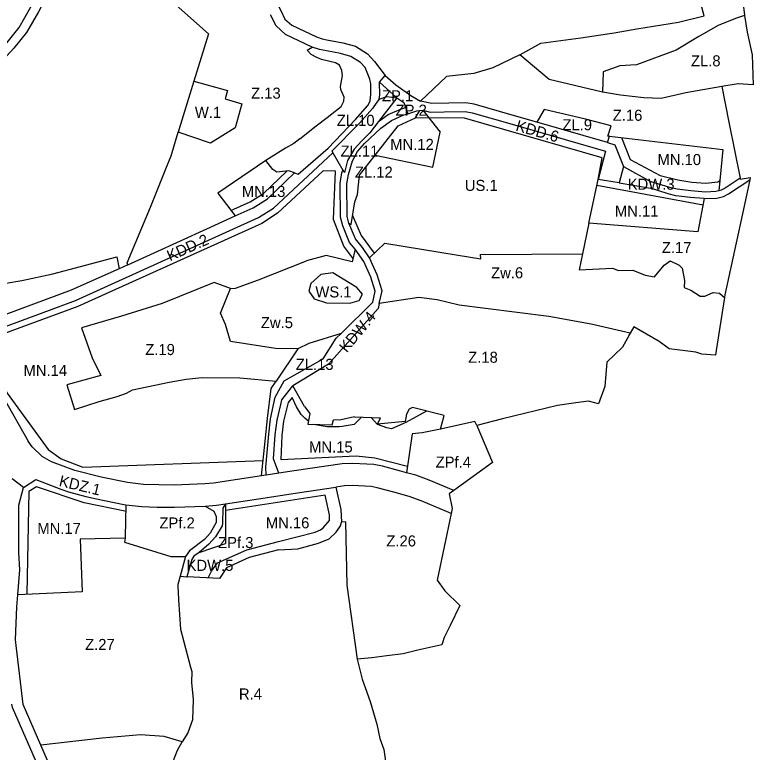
# Model space of a CAD drawing. Extents: x 7425478 to 7427982, y 5538517 to 5541171.
# Drawn here: x 7426110 to 7426777, y 5539161 to 5539827 of the extents above; entities that cross this region are included whole.
import ezdxf

# ---------------------------------------------------------------- set-up
doc = ezdxf.new("R2010")
doc.units = 0
for name, color, linetype in [('linie_rozgraniczajace', 7, 'Continuous'), ('linie_zabudowy_nieprzekraczalne', 7, 'Continuous'), ('oznaczenia_przeznaczen', 7, 'Continuous')]:
    doc.layers.add(name, color=color, linetype=linetype)

msp = doc.modelspace()

# ---------------------------------------------------------------- linework, layer by layer
at = {"layer": 'linie_rozgraniczajace'}
for p, q in [((7426285, 5539810.09), (7426271.89, 5539767.33)), ((7426439.61, 5539766.29), (7426444.81, 5539772.3)), ((7426455.35, 5539752.15), (7426439.61, 5539766.29)), ((7426455.35, 5539752.15), (7426438.67, 5539730.7)), ((7426463.07, 5539743.41), (7426465.29, 5539737.72)), ((7426475.94, 5539740.64), (7426478.73, 5539740.85)), ((7426478.73, 5539740.85), (7426494.38, 5539721.07)), ((7426645.63, 5539711.74), (7426581.74, 5539730.17)), ((7426647.49, 5539717.47), (7426646.05, 5539717.64)), ((7426397.35, 5539702.43), (7426406.5, 5539686.89)), ((7426643.73, 5539703.89), (7426637.31, 5539678.48)), ((7426749.94, 5539705.41), (7426746.33, 5539668.14)), ((7426406.5, 5539686.89), (7426407.9, 5539684.53)), ((7426660.09, 5539690.13), (7426656.36, 5539675.2)), ((7426283.56, 5539633.75), (7426309.14, 5539645.38)), ((7426628.89, 5539638.83), (7426623.22, 5539611.25)), ((7426212.06, 5539601.25), (7426204.28, 5539597.74)), ((7426204.28, 5539597.74), (7426172.52, 5539583.41)), ((7426365.83, 5539525.31), (7426346.21, 5539496)), ((7426371.89, 5539473.29), (7426361.19, 5539491.88)), ((7426371.89, 5539473.29), (7426376.65, 5539466.93)), ((7426437.87, 5539457.23), (7426440.63, 5539463)), ((7426348.68, 5539412.92), (7426337.3, 5539411.17)), ((7426117.82, 5539399.93), (7426107.74, 5539407.9)), ((7426337.3, 5539411.17), (7426333.03, 5539410.51)), ((7426300.44, 5539385.25), (7426300.52, 5539349.55)), ((7426276.69, 5539341.46), (7426300.52, 5539349.55))]:
    msp.add_line(p, q, dxfattribs=at)
for points in [[(7426172.93, 5539910.75), (7426157.78, 5539880.88), (7426131.38, 5539829.96), (7426120.78, 5539811.26), (7426109.12, 5539796.88), (7426076.6, 5539761.74), (7426068.87, 5539756.4), (7426052.03, 5539754.96), (7426040.49, 5539757.6), (7426024.63, 5539763.12), (7426003.8, 5539773.22), (7425997.61, 5539775.55), (7425990.1, 5539777.21), (7425982.57, 5539778.07)], [(7426172.93, 5539910.75), (7426199.52, 5539886.77), (7426237.04, 5539852.97), (7426285, 5539810.09)], [(7425861.28, 5539789.58), (7425876.14, 5539788.48), (7425917.05, 5539790.68), (7425930.12, 5539791.21), (7425946.2, 5539790.43), (7425991.44, 5539785.11), (7425999.89, 5539783.23), (7426006.95, 5539780.58), (7426027.7, 5539770.52), (7426042.71, 5539765.3), (7426052.59, 5539763.04), (7426066.07, 5539764.19), (7426071.32, 5539767.83), (7426103.07, 5539802.12), (7426114.14, 5539815.78), (7426124.35, 5539833.77), (7426150.65, 5539884.52), (7426159.34, 5539901.8)], [(7426341.76, 5539847.53), (7426350.65, 5539830.3), (7426354.22, 5539823.36), (7426360.39, 5539817.82), (7426382.72, 5539807.31), (7426387.89, 5539805.46), (7426392.07, 5539804.68), (7426406.6, 5539801.94), (7426417.95, 5539798.68), (7426428.88, 5539791.94), (7426435.25, 5539784.9), (7426444.81, 5539772.3)], [(7426768.52, 5539834.05), (7426769.46, 5539826.99), (7426769.54, 5539826.5), (7426771.95, 5539811.37), (7426776.4, 5539790.88), (7426777.36, 5539763.92), (7426763.76, 5539764.86), (7426748.98, 5539762.31), (7426755.39, 5539730.27), (7426765.55, 5539679.57), (7426765.7, 5539678.8), (7426774.69, 5539680.3), (7426774.22, 5539678.13), (7426767.58, 5539647.36), (7426751.75, 5539574), (7426751.28, 5539571.84), (7426751.27, 5539571.76), (7426743.93, 5539523.95), (7426743.21, 5539519.72), (7426730.8, 5539520.4), (7426725.56, 5539522.24), (7426701.31, 5539525.35), (7426692.21, 5539532.01), (7426680.76, 5539538.65), (7426669.32, 5539545.29), (7426666.18, 5539539.43), (7426666.07, 5539539.46), (7426666.03, 5539539.39), (7426665.03, 5539537.57), (7426665.14, 5539537.55), (7426659.14, 5539526.99), (7426645.04, 5539513.3), (7426643.15, 5539491.25), (7426637.58, 5539475.74), (7426628.35, 5539478.04), (7426617.12, 5539476.46), (7426600.57, 5539474.13), (7426550.91, 5539461.99), (7426527.49, 5539456.05), (7426541.81, 5539422.74), (7426506.76, 5539397.33), (7426502.62, 5539394.33), (7426505.39, 5539381.09), (7426504.43, 5539376.49), (7426491.73, 5539316.21), (7426498.72, 5539306.75), (7426512.27, 5539293.31), (7426503.42, 5539275.38), (7426497.96, 5539264.52), (7426496.44, 5539259.78), (7426495.87, 5539258.02), (7426474.37, 5539252.97), (7426460.89, 5539249.8), (7426446.27, 5539247.88), (7426432.78, 5539246.23), (7426419.48, 5539244.98), (7426423.98, 5539226.92), (7426431.18, 5539206.84), (7426437.31, 5539186.31), (7426439.93, 5539173.23), (7426443.46, 5539163.33), (7426447.85, 5539134.04)], [(7426566.31, 5539790.94), (7426585.56, 5539801.43), (7426621.44, 5539806.39), (7426651.66, 5539810.88), (7426672.2, 5539814.35), (7426709.79, 5539820.37), (7426732.96, 5539826.26), (7426730.15, 5539837.31)], [(7426378.9, 5539798.05), (7426354.8, 5539809.4), (7426346.17, 5539817.15), (7426341, 5539827.19)], [(7426769.54, 5539826.5), (7426761.3, 5539823.94), (7426745.75, 5539817.53), (7426728.11, 5539807.63), (7426707.67, 5539795.31), (7426671.73, 5539781.82), (7426656.78, 5539781.14), (7426641.67, 5539775.58), (7426641.12, 5539757.11)], [(7426362.77, 5539684.28), (7426366.04, 5539683.02), (7426393.22, 5539706.79), (7426417.96, 5539732.64), (7426429.18, 5539745.33), (7426431.25, 5539749.27), (7426431.92, 5539755.33), (7426431.76, 5539764.77), (7426430.9, 5539769.11), (7426426.66, 5539779.49), (7426422.42, 5539784.18), (7426413.87, 5539789.45), (7426404.29, 5539792.2), (7426385.27, 5539795.78), (7426378.9, 5539798.05)], [(7426367.55, 5539715.13), (7426382.31, 5539726.87), (7426392.47, 5539734.25), (7426404.94, 5539744.24), (7426407.37, 5539749.01), (7426407.68, 5539752.88), (7426404.73, 5539759.58), (7426404.43, 5539762.37), (7426406.07, 5539772.45), (7426405.74, 5539776.96), (7426403.35, 5539781.8), (7426399.83, 5539783.86), (7426387.32, 5539786.82), (7426382.91, 5539788.45), (7426377.92, 5539791.33), (7426374.27, 5539795.32), (7426378.9, 5539798.05)], [(7426566.31, 5539790.94), (7426542.17, 5539779.37), (7426524.88, 5539774.18), (7426500.27, 5539771.29), (7426476.54, 5539749.14)], [(7426641.12, 5539757.11), (7426592.95, 5539768.6), (7426566.31, 5539790.94)], [(7426271.89, 5539767.33), (7426302.28, 5539758.73), (7426300.12, 5539751.09), (7426315.22, 5539746.81), (7426309.07, 5539725.09), (7426287.05, 5539711.16), (7426257.77, 5539720.98)], [(7426271.89, 5539767.33), (7426259.88, 5539727.9), (7426257.77, 5539720.98)], [(7426439.36, 5539750.86), (7426439.93, 5539754.96), (7426439.61, 5539766.29)], [(7426444.81, 5539772.3), (7426454.43, 5539763.89), (7426467.85, 5539754.19), (7426476.54, 5539749.14)], [(7426748.98, 5539762.31), (7426716.58, 5539756.73), (7426694.27, 5539751.68), (7426678.42, 5539752.15), (7426657.52, 5539754.47), (7426641.12, 5539757.11)], [(7426439.36, 5539750.86), (7426446.33, 5539753.35), (7426455.35, 5539752.15)], [(7426439.36, 5539750.86), (7426437.11, 5539748.26), (7426433.16, 5539742.38), (7426421.65, 5539729.2), (7426396.48, 5539703.9), (7426397.35, 5539702.43)], [(7426455.35, 5539752.15), (7426461.51, 5539747.91), (7426463.07, 5539743.41)], [(7426581.74, 5539730.17), (7426559.6, 5539736.56), (7426525.13, 5539746.47), (7426517.76, 5539747.75), (7426486.83, 5539747.12), (7426476.54, 5539749.14)], [(7426435.7, 5539700.26), (7426456.62, 5539726.96), (7426472.23, 5539734.18), (7426475.94, 5539740.64)], [(7426438.67, 5539730.7), (7426447.45, 5539737), (7426459.6, 5539742.34), (7426463.07, 5539743.41)], [(7426465.29, 5539737.72), (7426473.48, 5539740.29), (7426475.94, 5539740.64)], [(7426478.73, 5539740.85), (7426485.52, 5539739.23), (7426498.13, 5539739.45)], [(7426498.13, 5539739.45), (7426516.92, 5539739.78), (7426523.33, 5539738.66), (7426557.38, 5539728.87), (7426643.73, 5539703.89)], [(7426646.05, 5539717.64), (7426648.86, 5539726.72), (7426625.91, 5539732.76), (7426588.5, 5539741.62), (7426581.74, 5539730.17)], [(7426411.99, 5539638.9), (7426410.51, 5539645.02), (7426410.1, 5539674.55), (7426411.55, 5539682.94), (7426415.36, 5539695.08), (7426419.74, 5539703.65), (7426426.16, 5539710.97), (7426440.83, 5539724.64), (7426450.48, 5539731.78), (7426461.69, 5539736.7), (7426465.29, 5539737.72)], [(7426438.67, 5539730.7), (7426430.76, 5539720.63), (7426423.64, 5539713.41), (7426416.82, 5539705.63), (7426410.7, 5539695.41), (7426407.9, 5539684.53)], [(7426232.79, 5539653.26), (7426246.65, 5539688), (7426251.31, 5539699.69), (7426257.77, 5539720.98)], [(7426435.7, 5539700.26), (7426487.95, 5539689.59), (7426494.38, 5539721.07)], [(7426367.55, 5539715.13), (7426362.28, 5539710.93), (7426354.75, 5539706.7), (7426336.84, 5539695.39)], [(7426645.63, 5539711.74), (7426647.49, 5539717.47)], [(7426647.49, 5539717.47), (7426749.94, 5539705.41)], [(7426645.63, 5539711.74), (7426652.43, 5539709.78), (7426660.09, 5539690.13)], [(7426069.33, 5539521.54), (7426078.15, 5539534.71), (7426082.62, 5539538.73), (7426164.84, 5539569.05), (7426330.34, 5539644.03), (7426343.82, 5539652.56), (7426397.35, 5539702.43)], [(7426411.99, 5539638.9), (7426413.91, 5539637.57), (7426417.21, 5539658.12), (7426419.69, 5539664.69), (7426421.59, 5539682.25), (7426435.7, 5539700.26)], [(7426336.84, 5539695.39), (7426293.49, 5539666.09), (7426309.14, 5539645.38)], [(7426362.77, 5539684.28), (7426357.79, 5539686.2), (7426346.86, 5539685.03), (7426343.16, 5539687.5), (7426336.84, 5539695.39)], [(7426417.67, 5539615.55), (7426412.66, 5539621.43), (7426406.44, 5539636.63), (7426404.52, 5539644.27), (7426404.09, 5539675.02), (7426405.71, 5539684.36), (7426406.5, 5539686.89)], [(7426660.09, 5539690.13), (7426685.2, 5539676.33)], [(7426309.14, 5539645.38), (7426325.57, 5539652.84), (7426338.44, 5539661), (7426362.77, 5539684.28)], [(7426765.55, 5539679.57), (7426752.06, 5539670.59), (7426748.24, 5539668.62), (7426746.33, 5539668.14)], [(7426628.89, 5539638.83), (7426637.31, 5539678.48)], [(7426656.36, 5539675.2), (7426637.31, 5539678.48)], [(7426656.36, 5539675.2), (7426684.46, 5539670.37)], [(7426746.33, 5539668.14), (7426743.68, 5539667.46), (7426734.34, 5539667.01), (7426720.98, 5539668.01), (7426708.65, 5539669.74), (7426702.14, 5539671.22), (7426685.2, 5539676.33)], [(7426733.12, 5539661.08), (7426744.58, 5539661.5), (7426750.38, 5539662.98), (7426755.1, 5539665.41), (7426774.22, 5539678.13)], [(7426733.12, 5539661.08), (7426720.37, 5539662.04), (7426707.53, 5539663.74), (7426700.57, 5539665.43), (7426684.46, 5539670.37)], [(7426733.12, 5539661.08), (7426727.42, 5539631.02), (7426628.89, 5539638.83)], [(7426212.06, 5539601.25), (7426211.71, 5539603.15), (7426232.79, 5539653.26)], [(7426212.06, 5539601.25), (7426283.56, 5539633.75)], [(7426430.55, 5539607.44), (7426424.37, 5539616.95), (7426417.85, 5539624.59), (7426411.99, 5539638.9)], [(7426430.55, 5539607.44), (7426444.33, 5539620.83), (7426510.66, 5539609.86), (7426531.15, 5539606.76), (7426530.96, 5539610.68), (7426623.22, 5539611.25)], [(7426417.67, 5539615.55), (7426414.89, 5539603.91), (7426391.35, 5539609.63), (7426373.69, 5539604.92)], [(7426425.41, 5539604.24), (7426417.67, 5539615.55)], [(7426169.45, 5539599.84), (7426202.25, 5539608.44), (7426204.28, 5539597.74)], [(7426439.44, 5539566.26), (7426441.89, 5539577.67), (7426437.54, 5539592.13), (7426430.55, 5539607.44)], [(7426623.22, 5539611.25), (7426620.14, 5539596.85), (7426650.3, 5539598.34), (7426655.56, 5539596.21), (7426668.61, 5539596.49), (7426679.63, 5539591.96), (7426688.13, 5539590.47), (7426696.79, 5539600.83), (7426702.18, 5539604.92), (7426710.54, 5539601.02), (7426713.22, 5539598.24), (7426715.34, 5539587.01), (7426714.88, 5539580.66), (7426720.85, 5539578.23), (7426729.36, 5539572.79), (7426733.54, 5539572.94), (7426741.17, 5539576.27), (7426746.82, 5539575.7), (7426751.27, 5539571.76)], [(7426053.91, 5539595.8), (7426087.71, 5539582.24), (7426116.53, 5539587.16), (7426144.44, 5539593.04), (7426169.45, 5539599.84)], [(7426304.91, 5539579.72), (7426309.37, 5539580.02), (7426330.35, 5539587.63), (7426373.69, 5539604.92)], [(7426404.95, 5539539.2), (7426433.7, 5539567.38), (7426435.71, 5539577.38), (7426431.91, 5539590.01), (7426425.41, 5539604.24)], [(7426172.52, 5539583.41), (7426161.08, 5539578.22), (7426077.37, 5539547.45), (7426070.54, 5539541.32), (7426060.68, 5539526.61)], [(7426304.91, 5539579.72), (7426290.27, 5539585.38), (7426243.33, 5539566.28)], [(7426365.83, 5539525.31), (7426345.59, 5539525.69), (7426304.98, 5539531.98), (7426300.38, 5539547.38), (7426295.81, 5539557.55), (7426304.91, 5539579.72)], [(7426243.33, 5539566.28), (7426206.48, 5539554.8)], [(7426439.44, 5539566.26), (7426438.5, 5539561.86), (7426393.45, 5539511.58), (7426361.19, 5539491.88)], [(7426666.03, 5539539.39), (7426630.76, 5539547.76), (7426592.73, 5539554.56), (7426535.43, 5539561.78), (7426511.77, 5539564.88), (7426491.6, 5539569.68), (7426475.06, 5539571.86), (7426439.44, 5539566.26)], [(7426206.48, 5539554.8), (7426170.48, 5539544.37), (7426180.03, 5539517.35), (7426187.95, 5539501.14), (7426156.97, 5539492.85), (7426164.15, 5539470.66), (7426186.34, 5539477.84), (7426202.69, 5539482.34), (7426211.07, 5539485.2), (7426216.52, 5539488.25)], [(7426337.3, 5539411.17), (7426337.06, 5539418.5), (7426339.49, 5539448.32), (7426341.14, 5539462.02), (7426345.3, 5539481.74), (7426353.61, 5539496.45), (7426388.83, 5539516.43), (7426400.55, 5539534.86), (7426404.95, 5539539.2)], [(7426404.95, 5539539.2), (7426375.77, 5539530.15), (7426365.83, 5539525.31)], [(7426070.57, 5539510.87), (7426090.07, 5539494.56), (7426098.94, 5539482.81), (7426122.19, 5539441.95)], [(7426216.52, 5539488.25), (7426249.67, 5539495.26), (7426264.8, 5539498.06), (7426279.45, 5539499.3), (7426313.3, 5539499.19), (7426346.21, 5539496)], [(7426333.03, 5539410.51), (7426336.37, 5539441.88), (7426338.54, 5539462.25), (7426341.68, 5539489.4), (7426346.21, 5539496)], [(7426350.44, 5539475.16), (7426351.45, 5539479.39), (7426361.19, 5539491.88)], [(7426348.68, 5539412.92), (7426343.85, 5539425.9), (7426345.46, 5539447.72), (7426347.07, 5539461.04), (7426350.44, 5539475.16)], [(7426494.84, 5539452.72), (7426497.98, 5539465.13), (7426469.35, 5539472.39), (7426466.52, 5539470.76), (7426463.99, 5539466.22), (7426462.9, 5539459.54), (7426437.87, 5539457.23)], [(7426376.65, 5539466.93), (7426374.8, 5539457.15), (7426396.87, 5539456.73), (7426397.98, 5539461.23)], [(7426417.18, 5539463.99), (7426407.76, 5539461.75), (7426403.49, 5539461.04), (7426397.98, 5539461.23)], [(7426417.18, 5539463.99), (7426440.63, 5539463)], [(7426527.49, 5539456.05), (7426525.85, 5539459.64), (7426494.84, 5539452.72)], [(7426494.84, 5539452.72), (7426478.29, 5539449.37), (7426469.02, 5539448.6)], [(7426469.02, 5539448.6), (7426464, 5539413.37)], [(7426333.03, 5539410.51), (7426289.6, 5539403.84), (7426281.82, 5539403.26), (7426254.09, 5539402.25), (7426226.3, 5539402.73), (7426211.84, 5539404.49), (7426188, 5539409.35), (7426164.19, 5539415.4), (7426143.13, 5539423.25), (7426134.8, 5539428), (7426125.63, 5539436.7), (7426122.19, 5539441.95)], [(7426464, 5539413.37), (7426457.77, 5539415.05), (7426442.39, 5539419.2), (7426434.63, 5539420.93), (7426428.05, 5539421.23), (7426415.2, 5539421.8), (7426405.78, 5539421.53), (7426362.55, 5539415.06), (7426348.68, 5539412.92)], [(7426506.76, 5539397.33), (7426484.62, 5539406.62), (7426472.55, 5539411.07), (7426464, 5539413.37)], [(7426117.82, 5539399.93), (7426129.04, 5539407.38), (7426151.76, 5539398.44), (7426158.47, 5539396.23), (7426174.13, 5539392.03), (7426183.75, 5539389.81), (7426208.63, 5539384.73), (7426210.38, 5539384.52)], [(7426112.9, 5539303.14), (7426114.7, 5539325.55), (7426113.6, 5539341.32), (7426113.69, 5539384.05), (7426117.82, 5539399.93)], [(7426300.44, 5539385.25), (7426340.35, 5539391.4), (7426365.54, 5539395.29), (7426400.17, 5539400.46)], [(7426504.43, 5539376.49), (7426500.08, 5539378.31), (7426477.24, 5539388.02), (7426466.47, 5539391.99), (7426452.57, 5539395.74), (7426437.61, 5539399.77), (7426431.98, 5539401.03), (7426415.04, 5539401.79), (7426408.03, 5539401.59), (7426400.17, 5539400.46)], [(7426400.17, 5539400.46), (7426404.64, 5539380.03), (7426405.18, 5539368.76)], [(7426210.38, 5539384.52), (7426209.91, 5539355.28), (7426209.79, 5539354.41)], [(7426210.38, 5539384.52), (7426224.83, 5539382.76), (7426238.76, 5539382.39), (7426254.36, 5539382.24), (7426281.97, 5539383.25)], [(7426281.97, 5539383.25), (7426289.95, 5539378.68), (7426292.13, 5539374), (7426291.92, 5539368.32), (7426286.54, 5539358.94), (7426281.36, 5539353.11), (7426267.92, 5539342.78), (7426264.35, 5539337.78)], [(7426300.44, 5539385.25), (7426298.04, 5539381.25), (7426297.9, 5539367.67), (7426297.34, 5539365.49), (7426291.44, 5539355.42), (7426285.54, 5539348.78), (7426276.69, 5539341.46)], [(7426281.97, 5539383.25), (7426292.2, 5539383.98), (7426300.44, 5539385.25)], [(7426348.21, 5539343.74), (7426365.76, 5539344.52), (7426384.55, 5539349.65), (7426394.07, 5539353.56), (7426400.39, 5539359.81), (7426404.39, 5539365.33), (7426405.18, 5539368.76)], [(7426408.88, 5539368.89), (7426405.18, 5539368.76)], [(7426408.88, 5539368.89), (7426409.98, 5539311.94), (7426419.48, 5539244.98)], [(7426209.79, 5539354.41), (7426169.26, 5539353.31), (7426170.94, 5539305.76), (7426112.9, 5539303.14)], [(7426209.79, 5539354.41), (7426209.27, 5539350.76), (7426251.07, 5539337.73), (7426264.35, 5539337.78)], [(7426348.21, 5539343.74), (7426321.92, 5539336.87), (7426301.24, 5539327.4), (7426294.95, 5539317.92), (7426265.47, 5539319.47)], [(7426276.69, 5539341.46), (7426271.82, 5539338.03), (7426270, 5539334.99), (7426265.47, 5539319.47)], [(7426264.35, 5539337.78), (7426259.46, 5539319.79)], [(7426259.46, 5539319.79), (7426257.44, 5539312.38), (7426257.47, 5539309.69), (7426257.66, 5539305.69), (7426258.13, 5539298.56), (7426259.9, 5539271.99), (7426268.94, 5539237.8), (7426269.93, 5539233.94), (7426269.78, 5539223.98), (7426271.14, 5539208.62), (7426270.54, 5539190.27), (7426266.45, 5539178.5), (7426261.32, 5539170.23)], [(7426259.46, 5539319.79), (7426265.47, 5539319.47)], [(7426115.75, 5539219.48), (7426110.76, 5539262.41), (7426112.04, 5539292.38), (7426112.9, 5539303.14)], [(7426133.53, 5539167.33), (7426117.62, 5539203.88), (7426115.75, 5539219.48)], [(7426019.32, 5539018.32), (7426129.7, 5539040.2), (7426134.42, 5539041.34), (7426137.76, 5539043.2), (7426141.67, 5539047.91), (7426142.89, 5539050.48), (7426143.53, 5539053.88), (7426141.59, 5539089.62), (7426135.87, 5539137), (7426107.86, 5539201.24), (7426107.49, 5539204.41)], [(7426261.32, 5539170.23), (7426245.09, 5539175.08), (7426223.61, 5539176.57), (7426189.1, 5539173.57), (7426133.53, 5539167.33)], [(7426151.82, 5539085.48), (7426151.56, 5539090.49), (7426145.63, 5539139.65), (7426133.53, 5539167.33)], [(7426253.18, 5539145.1), (7426253, 5539151.86), (7426257.18, 5539162.75), (7426261.32, 5539170.23)]]:
    msp.add_lwpolyline(points, dxfattribs=at)
msp.add_lwpolyline([(7426421.36, 5539568.91), (7426424.13, 5539574.62), (7426419.08, 5539580.83), (7426397.36, 5539594.04), (7426386.5, 5539592.49), (7426377.47, 5539584.44), (7426375.69, 5539577.56), (7426380.57, 5539570.46), (7426391.65, 5539566.91), (7426412.71, 5539566.69)], close=True, dxfattribs=at)
at = {"layer": 'linie_zabudowy_nieprzekraczalne'}
for p, q in [((7426658.45, 5539716.37), (7426666.2, 5539696.47)), ((7426732.05, 5539655.3), (7426636.15, 5539673)), ((7426360.65, 5539481.44), (7426356.98, 5539476.73))]:
    msp.add_line(p, q, dxfattribs=at)
for points in [[(7426637.31, 5539678.48), (7426640.84, 5539697.8), (7426516.45, 5539733.77), (7426472.23, 5539734.18)], [(7426666.2, 5539696.47), (7426693.4, 5539682.08), (7426709.18, 5539678.18), (7426721.84, 5539675.97), (7426734.45, 5539675.02), (7426745.38, 5539676.15), (7426747.22, 5539677.35)], [(7426415.67, 5539607.16), (7426407.47, 5539618.26), (7426398.09, 5539642.34), (7426399.86, 5539685.77), (7426388.87, 5539686.22), (7426347.5, 5539647.79), (7426333.19, 5539638.73), (7426167.12, 5539563.5), (7426079.94, 5539531.72)], [(7426305.42, 5539650.3), (7426322.71, 5539658.14), (7426334.73, 5539665.74), (7426355.89, 5539686)], [(7426415.22, 5539645.73), (7426423.04, 5539627.75), (7426434.89, 5539611.65)], [(7426092.64, 5539502.71), (7426103.07, 5539485.18), (7426140.12, 5539434.3), (7426151.92, 5539426.03), (7426171.4, 5539418.56), (7426334.52, 5539424.54)], [(7426375.84, 5539459.73), (7426372.05, 5539462.64), (7426368.97, 5539466.03), (7426364.59, 5539473), (7426360.65, 5539481.44)], [(7426356.98, 5539476.73), (7426352.98, 5539459.98), (7426351.43, 5539447.14), (7426350.56, 5539425.34)], [(7426482.13, 5539469.15), (7426463.56, 5539458.74), (7426450.55, 5539453.05), (7426446.15, 5539453.86), (7426437.97, 5539456.96), (7426432.19, 5539463.36)], [(7426423.24, 5539463.74), (7426416.64, 5539457.09), (7426405.91, 5539455.13), (7426403.23, 5539454.92), (7426392.37, 5539454.93), (7426380.07, 5539457.05)], [(7426350.56, 5539425.34), (7426418.6, 5539428.71), (7426435.43, 5539426.9), (7426464.85, 5539419.35)], [(7426210.99, 5539378.51), (7426172.68, 5539386.21), (7426129.71, 5539400.67), (7426122.88, 5539396.53), (7426122.88, 5539396.53), (7426120.94, 5539303.99)], [(7426284.87, 5539318.45), (7426287.77, 5539324.47), (7426293.33, 5539331.85), (7426293.33, 5539331.85), (7426319.63, 5539343.6), (7426348.51, 5539351.21), (7426381.55, 5539359.75), (7426386.43, 5539361.77), (7426388.74, 5539363.67), (7426394.45, 5539370.2), (7426394.4, 5539375.22), (7426390.67, 5539393), (7426300.45, 5539379.35)]]:
    msp.add_lwpolyline(points, dxfattribs=at)

# ---------------------------------------------------------------- texts
at = {"layer": 'oznaczenia_przeznaczen'}
for s, p in [('ZL.8', (7426721.08, 5539780.58)), ('Z.13', (7426323.59, 5539751.37)), ('ZP.1', (7426441.88, 5539749.01)), ('ZP.2', (7426454.15, 5539735.99)), ('W.1', (7426272.76, 5539734.02)), ('Z.16', (7426650.41, 5539731.38)), ('ZL.10', (7426400.98, 5539726.81)), ('ZL.9', (7426604.92, 5539722.81)), ('MN.12', (7426449.32, 5539705.08)), ('ZL.11', (7426404.4, 5539698.98)), ('MN.10', (7426690.83, 5539691.4)), ('ZL.12', (7426417.42, 5539680.09)), ('KDW.3', (7426663.92, 5539669.12)), ('MN.13', (7426315.19, 5539662.57)), ('US.1', (7426516.72, 5539668.01)), ('MN.11', (7426652.34, 5539644.8)), ('Z.17', (7426694.78, 5539611.9)), ('Zw.6', (7426540.47, 5539589.04)), ('WS.1', (7426381.68, 5539571.79)), ('Zw.5', (7426332.45, 5539544.03)), ('Z.19', (7426227.96, 5539519.73)), ('Z.18', (7426519.79, 5539512.75)), ('ZL.13', (7426363.95, 5539506.32)), ('MN.14', (7426117.9, 5539500.79)), ('MN.15', (7426375.98, 5539431.67)), ('ZPf.4', (7426490.33, 5539417.99)), ('ZPf.2', (7426240.76, 5539363.01)), ('MN.16', (7426336.88, 5539363.19)), ('MN.17', (7426130.4, 5539358.11)), ('ZPf.3', (7426293.77, 5539345.33)), ('Z.26', (7426445.82, 5539346.8)), ('KDW.5', (7426265.29, 5539324.71)), ('Z.27', (7426173.57, 5539253.23)), ('R.4', (7426312.62, 5539208.48))]:
    msp.add_text(s, height=10, dxfattribs=at).set_placement(p)
for s, rotation, p in [('KDD.6', 344.1155, (7426562.05, 5539722.61)), ('KDD.2', 23.99707, (7426250.26, 5539604.35)), ('KDW.4', 50.2721, (7426410, 5539521.33)), ('KDZ.1', 346.52375, (7426149.39, 5539401.55))]:
    msp.add_text(s, height=10, rotation=rotation, dxfattribs=at).set_placement(p)

doc.saveas('drawing.dxf')
